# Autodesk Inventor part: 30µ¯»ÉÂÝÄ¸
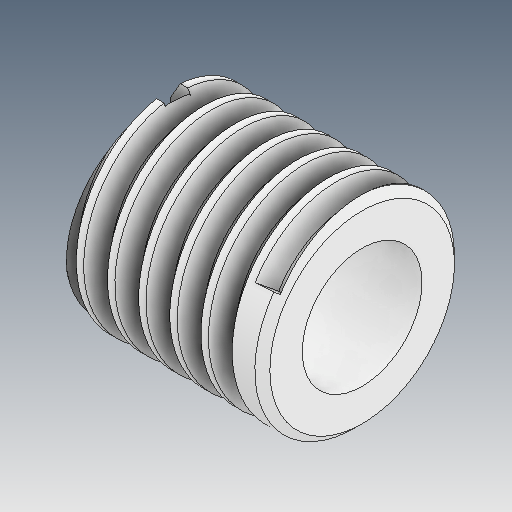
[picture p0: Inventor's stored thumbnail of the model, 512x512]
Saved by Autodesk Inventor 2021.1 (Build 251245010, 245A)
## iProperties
Created: 2021-05
Part Number: 30µ¯»ÉÂÝÄ¸
Material: Ogólny
Document SubType Name: Modeling
Designer: user
Density: 1 g/cm^3
Appearance: Domyślna
Author: user
Revision Number: ÈÎºÎ
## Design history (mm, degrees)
feature "ÊäÈë1"
node "Bryła1"
